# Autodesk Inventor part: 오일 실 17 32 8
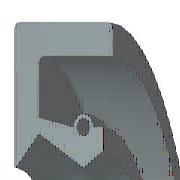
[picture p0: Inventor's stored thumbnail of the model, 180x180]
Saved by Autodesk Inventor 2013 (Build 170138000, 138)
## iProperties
IsCustomPart: 1
Created: 2012-02
Part Number: 오일 실 17 32 8
Material: 고무
Description: 오일-실
Document SubType Name: Modeling
Standard: KS B 2804
Designer: mduedu
Standards Organization: KS
Language: ko-KR
Size Designation: D - 17 32 8
Categories: <MemberInstance><Categories><Category DisplayName="샤프트 부품" InternalName="7f7aeb1f-a693-4053-b835-cee3144e0d98" Mnemonic="SHFT"><Category DisplayName="실링" Intern
Density: 0.93 g/cm^3
Author: mduedu
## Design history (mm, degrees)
revolve "본체" stored, may be unused: angle "d17" = 90 deg
revolve "스프링1" stored, may be unused: angle "d18" = 90 deg
body "Solid1"
sketch "스케치1"
  geometry: L1 (0, 16)-(8, 16); L2 (8, 14.25)-(1.75, 14.25); L3 (1.75, 10.25)-(4.9, 8.5); L4 (4.9, 8.5)-(0, 8.5); L5 (0, 0)-(9.586, 0) reference; L6 (4.9, 8.5)-(6.3, 9.375); L7 (0, 18)-(0, -3) reference; L8 (-1.941, 0)-(11.507, 0) reference; L9 (4.2, 10.6)-(1.75, 11.21); L10 (1.75, 11.21)-(1.75, 14.25); L11 (0, 16)-(0, 8.588); L12 (4.9, 8.5)-(0, 8.5); L13 (1.75, 10.25)-(0.152, 8.528); L14 (8, 16)-(8, 14.25); L15 (5.6, 10.6)-(6.3, 10.6); L16 (6.3, 10.6)-(6.3, 9.375); C1 r 0.455 at (4.9, 10.6); A1 r 0.7 centre (4.9, 10.6) between (5.6, 10.6) and (4.2, 10.6); A2 r 0.088 centre (0.088, 8.588) between (0, 8.588) and (0.152, 8.528); 1 further point
  constraints: 28 end point, 5 horizontal alignment, 5 point on line, 4 point on circle, 4 vertical alignment, 3 centre point, 3 tangent, 2 collinear, 2 horizontal, 2 perpendicular, 1 coincident, 1 parallel
  dimensions: "d0" = 32 diameter of L1 L5 (= SD2); "d1" = 1.75 distance of L1.end L2.start (= SD); "d2" = 0.91 diameter of C1 (= SPDI); "d3" = 1.4 diameter of A1 (= SPDA); "d4" = 17 diameter of L3.end L5 (= NND); "d5" = 20.5 diameter of L3.start L5 (= TKDM); "d7" = 22.42 diameter of L9.end L5 (= TKDM + 0.24 x SWDT); "d8" = 1.75 distance between parallel lines of L11 L10 (= SD); "d9" = 4.9 distance from line of L11 C1.centre (= SPDST); "d10" = 21.2 diameter of C1.centre L5 (= HLDM); "d11" = 0.0875 radius of A2 (= 0.25 x LAB); "d12" = 6.3 distance between parallel lines of L11 L16 (= SDI); "d13" = 18.75 diameter of L6.end L5 (= ABDM); "d14" = 8 distance from line of L11 L1.end (= SWDT)
fillet "모깎기1" dims "d6" = 0.3 (= RR)
other parameters: "SD2" = 32 [user parameter; used in 1 equation term], "SWDT" = 8 [user parameter; used in 2 equation terms], "RR" = 0.3 [user parameter; used in 1 equation term], "SD" = 1.75 [user parameter; used in 2 equation terms], "NND" = 17 [user parameter; used in 1 equation term], "SPDA" = 1.4 [user parameter; used in 1 equation term], "SPDI" = 0.91 [user parameter; used in 1 equation term], "TKDM" = 20.5 [user parameter; used in 2 equation terms], "HLDM" = 21.2 [user parameter; used in 1 equation term], "ABDM" = 18.75 [user parameter; used in 1 equation term], "SDI" = 6.3 [user parameter; used in 1 equation term], "SPDST" = 4.9 [user parameter; used in 1 equation term], "LAB" = 0.35 [user parameter; used in 1 equation term], "d15" = 0, "d16" = 0, "d19" = 0
